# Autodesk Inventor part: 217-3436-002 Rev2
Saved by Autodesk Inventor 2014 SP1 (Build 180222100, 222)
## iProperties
Created: 2014-06
Part Number: 217-3436-002 Rev2
Material: Aluminum 6061
Document SubType Name: Modeling
Designer: Michael
Density: 2.71 g/cm^3
Appearance: Aluminum - Flat
Author: Michael
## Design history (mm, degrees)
node "217-3436-002 Rev2.ipt1"
node "Fillet2"
node "Base1"
